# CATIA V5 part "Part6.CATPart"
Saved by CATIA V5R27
Part number: Part6
Bounding box of the stored display mesh (mm): x -9.5 to 9.5, y -1 to 4, z 109 to 128
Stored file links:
  E:\university\my-thesis\My Thesis Publication\Final-Updata\CAD\Part6.CATPart
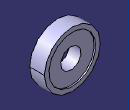
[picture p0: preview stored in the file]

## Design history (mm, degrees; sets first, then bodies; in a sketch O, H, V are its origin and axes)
Set1
  Sketch1 on zx-plane, origin (0, 0, 0), H (-1, 0, 0), V (0, 0, 1)
    projected circle E1 centre (0, 118.5) radius 9.5 from edge of DatumCurve1
    projected circle E2 centre (0, 118.5) radius 3.5 from edge of DatumCurve2
  DatumCurve1
  DatumCurve2
  Sketch2 on end face of Pad1, origin (0, 4, 0), H (-1, 0, 0), V (0, 0, 1)
    point P1 (0.3126, 121.986)
    projected circle E1 centre (0, 118.5) radius 3.5 from edge [end face of Pad1 | face of Pad1 from Sketch1.E2]
    offset circle E2 centre (0, 118.5) radius 8 from edge [end face of Pad1 | face of Pad1 from Sketch1.E2]
  Sketch3 on start face of Pad1, origin (0, -1, 0), H (1, 0, 0), V (0, 0, 1)
    projected circle E1 centre (0, 118.5) radius 3.5 from edge [face of Pad1 from Sketch1.E2 | start face of Pad1]
    offset circle E2 centre (0, 118.5) radius 8 from edge [face of Pad1 from Sketch1.E2 | start face of Pad1]
Body1 (main body)
  Pad1: profile Sketch1, direction (0, 1, 0), length 4, opposite side length 1
  Pocket1: profile Sketch2, direction (0, -1, 0), length 0.5
  Pocket2: profile Sketch3, direction (0, 1, 0), length 0.5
